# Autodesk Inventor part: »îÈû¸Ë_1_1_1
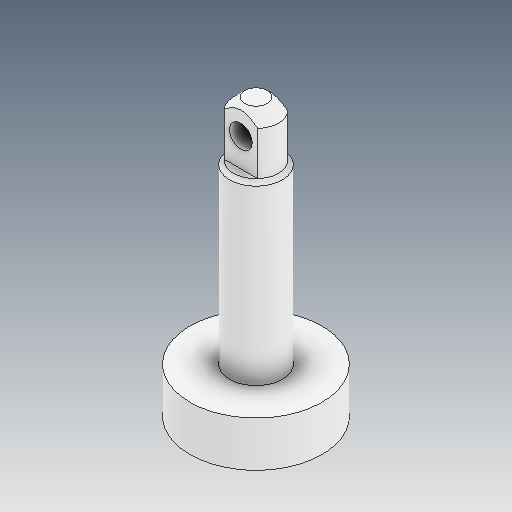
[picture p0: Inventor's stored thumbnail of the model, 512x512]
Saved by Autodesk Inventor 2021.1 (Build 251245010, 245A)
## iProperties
Created: 2021-05
Part Number: »îÈû¸Ë_1_1_1
Material: Ogólny
Document SubType Name: Modeling
Designer: user
Density: 1 g/cm^3
Appearance: Domyślna
Author: user
Revision Number: ÈÎºÎ
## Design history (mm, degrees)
feature "ÊäÈë1"
node "Bryła1"
